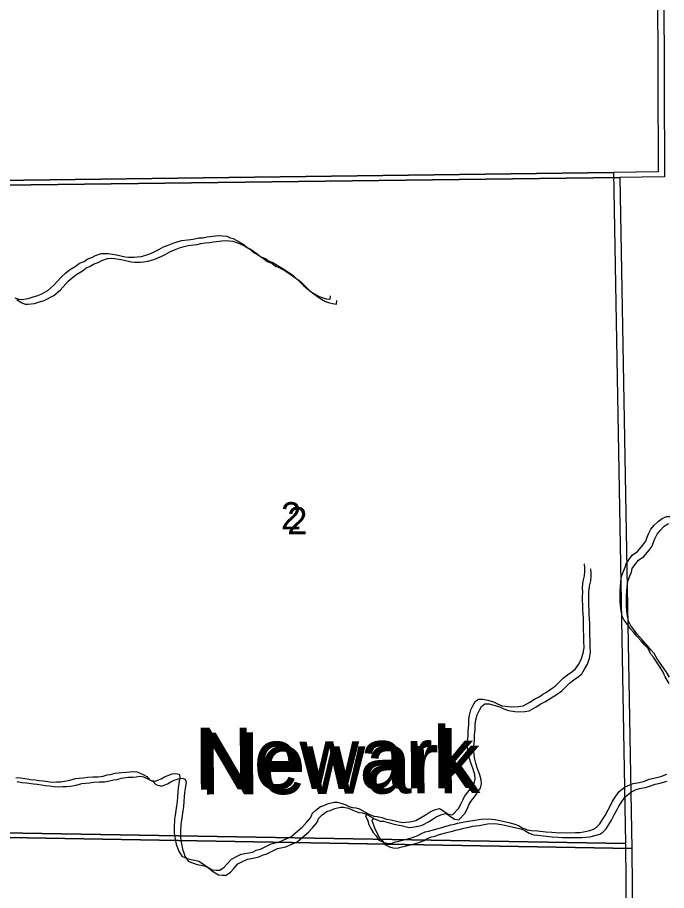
# Model space of a CAD drawing. Extents: x -21.1 to 50.3, y -4.9 to 22.1.
# Drawn here: x 48.245 to 49.24, y 18.636 to 19.975 of the extents above; entities that cross this region are included whole.
import ezdxf

# ---------------------------------------------------------------- set-up
doc = ezdxf.new("R2010")
doc.units = 0
for name, color, linetype in [('GM_X_Minor_River', 7, 'Continuous'), ('GM_X_Minor_River_Text', 7, 'Continuous'), ('GM_X_Section', 7, 'Continuous'), ('GM_X_Section_Text', 7, 'Continuous')]:
    doc.layers.add(name, color=color, linetype=linetype)

msp = doc.modelspace()

# ---------------------------------------------------------------- linework, layer by layer
at = {"layer": 'GM_X_Minor_River'}
for points in [[(48.4561, 19.6161), (48.4614, 19.6188), (48.4683, 19.623), (48.4755, 19.6257), (48.4831, 19.6288), (48.4907, 19.6311), (48.4964, 19.6327), (48.5051, 19.6335), (48.5105, 19.6343), (48.5162, 19.6354), (48.5226, 19.6366), (48.5291, 19.637), (48.5352, 19.6382), (48.5401, 19.6386), (48.5481, 19.6398), (48.5542, 19.6402), (48.5592, 19.6398), (48.5653, 19.6391), (48.5706, 19.6369), (48.5752, 19.6357), (48.5843, 19.6309), (48.5923, 19.6263), (48.5969, 19.6218), (48.603, 19.6188), (48.6122, 19.6124), (48.6176, 19.6079), (48.6248, 19.6053), (48.6306, 19.6011), (48.6359, 19.5989), (48.6451, 19.5936), (48.6531, 19.5887), (48.6619, 19.5827), (48.6665, 19.5793), (48.6714, 19.5747), (48.6772, 19.5691), (48.6829, 19.5638), (48.689, 19.5585), (48.6955, 19.5536), (48.7009, 19.5502), (48.707, 19.5468), (48.7131, 19.5446), (48.718, 19.5435), (48.7238, 19.5427), (48.7245, 19.5481)], [(48.4658, 19.6086), (48.4711, 19.6113), (48.4779, 19.6155), (48.4851, 19.6182), (48.4927, 19.6213), (48.5003, 19.6236), (48.506, 19.6252), (48.5148, 19.626), (48.5201, 19.6268), (48.5258, 19.6279), (48.5323, 19.6291), (48.5387, 19.6295), (48.5448, 19.6307), (48.5498, 19.6311), (48.5578, 19.6323), (48.5638, 19.6327), (48.5688, 19.6323), (48.5749, 19.6316), (48.5802, 19.6294), (48.5848, 19.6282), (48.594, 19.6234), (48.602, 19.6188), (48.6066, 19.6143), (48.6127, 19.6113), (48.6219, 19.6049), (48.6272, 19.6004), (48.6345, 19.5978), (48.6402, 19.5936), (48.6455, 19.5914), (48.6547, 19.5861), (48.6627, 19.5812), (48.6715, 19.5752), (48.6761, 19.5718), (48.6811, 19.5672), (48.6868, 19.5616), (48.6925, 19.5563), (48.6987, 19.551), (48.7052, 19.5461), (48.7105, 19.5427), (48.7166, 19.5393), (48.7227, 19.5371), (48.7277, 19.536), (48.7334, 19.5352), (48.7341, 19.5406)], [(48.2407, 19.545), (48.2464, 19.5428), (48.251, 19.5424), (48.2609, 19.5436), (48.2673, 19.5459), (48.2757, 19.5482), (48.281, 19.5506), (48.2863, 19.5536), (48.2909, 19.5559), (48.3004, 19.564), (48.3049, 19.5693), (48.3125, 19.5777), (48.3185, 19.5831), (48.3242, 19.5876), (48.3344, 19.5938), (48.3398, 19.598), (48.3466, 19.6007), (48.3515, 19.6041), (48.3595, 19.6072), (48.3644, 19.6095), (48.3728, 19.6126), (48.3789, 19.613), (48.3838, 19.6127), (48.3903, 19.6116), (48.3964, 19.6105), (48.4094, 19.6075), (48.4151, 19.6071), (48.4231, 19.6072), (48.428, 19.6076), (48.4349, 19.6084), (48.4444, 19.6111), (48.4501, 19.6134), (48.4561, 19.6161)], [(48.2438, 19.5424), (48.2503, 19.5375), (48.2561, 19.5353), (48.2606, 19.5349), (48.2705, 19.5361), (48.277, 19.5384), (48.2853, 19.5407), (48.2907, 19.5431), (48.296, 19.5461), (48.3005, 19.5484), (48.31, 19.5565), (48.3145, 19.5618), (48.3221, 19.5702), (48.3282, 19.5756), (48.3338, 19.5801), (48.3441, 19.5863), (48.3494, 19.5905), (48.3562, 19.5932), (48.3612, 19.5966), (48.3691, 19.5997), (48.3741, 19.602), (48.3824, 19.6051), (48.3885, 19.6055), (48.3935, 19.6052), (48.3999, 19.6041), (48.406, 19.6029), (48.419, 19.6), (48.4247, 19.5996), (48.4327, 19.5997), (48.4376, 19.6001), (48.4445, 19.6009), (48.454, 19.6036), (48.4597, 19.6059), (48.4658, 19.6086)], [(49.2436, 18.9537), (49.2374, 18.9636), (49.2343, 18.9708), (49.2297, 18.9787), (49.2251, 18.9852), (49.2194, 18.9939), (49.2155, 18.9988), (49.2113, 19.0071), (49.2063, 19.0124), (49.2006, 19.0188), (49.1941, 19.0264), (49.1891, 19.0321), (49.1845, 19.0374), (49.1807, 19.0423), (49.1749, 19.0506), (49.1718, 19.0567), (49.1695, 19.068), (49.1687, 19.0791), (49.1686, 19.0958), (49.1696, 19.1091), (49.17, 19.1144), (49.1711, 19.1193), (49.1741, 19.127), (49.1764, 19.1319), (49.1775, 19.1372), (49.1828, 19.1449), (49.1869, 19.1502), (49.1953, 19.1559), (49.2032, 19.1655), (49.2077, 19.1716), (49.21, 19.1777), (49.2122, 19.183), (49.2156, 19.1902), (49.2202, 19.1956), (49.2266, 19.2021), (49.233, 19.2063), (49.2395, 19.2094), (49.2448, 19.2098)], [(49.244, 18.9633), (49.2394, 18.9712), (49.2348, 18.9777), (49.229, 18.9864), (49.2252, 18.9913), (49.2209, 18.9996), (49.216, 19.0049), (49.2102, 19.0113), (49.2037, 19.0189), (49.1987, 19.0246), (49.1941, 19.0299), (49.1903, 19.0348), (49.1845, 19.0431), (49.1815, 19.0492), (49.1791, 19.0605), (49.1783, 19.0716), (49.1782, 19.0883), (49.1793, 19.1016), (49.1796, 19.1069), (49.1807, 19.1118), (49.1837, 19.1195), (49.186, 19.1244), (49.1871, 19.1297), (49.1924, 19.1374), (49.1965, 19.1427), (49.2049, 19.1484), (49.2128, 19.158), (49.2174, 19.1641), (49.2196, 19.1702), (49.2219, 19.1755), (49.2253, 19.1827), (49.2298, 19.1881), (49.2362, 19.1946), (49.2427, 19.1988)], [(49.1112, 19.0673), (49.1112, 19.0723), (49.1108, 19.0825), (49.1107, 19.0875), (49.1111, 19.0928), (49.111, 19.1015), (49.1118, 19.1103), (49.114, 19.1186), (49.1143, 19.1255), (49.1143, 19.1304), (49.1139, 19.1369)], [(49.1209, 19.0598), (49.1208, 19.0648), (49.1204, 19.075), (49.1204, 19.08), (49.1207, 19.0853), (49.1207, 19.094), (49.1214, 19.1028), (49.1236, 19.1111), (49.124, 19.118), (49.124, 19.1229), (49.1235, 19.1294)], [(48.596, 18.6934), (48.6048, 18.6953), (48.6105, 18.698), (48.6173, 18.6999), (48.6336, 18.708), (48.6462, 18.7107), (48.653, 18.7138), (48.6636, 18.7184), (48.6708, 18.7245), (48.6811, 18.7333), (48.6871, 18.7398), (48.6939, 18.7475), (48.6969, 18.7547), (48.7019, 18.7597), (48.7091, 18.765), (48.7144, 18.7666), (48.7212, 18.7696), (48.73, 18.7716), (48.7349, 18.7716), (48.7421, 18.7698), (48.7479, 18.7675), (48.7528, 18.7653), (48.7582, 18.7634), (48.7631, 18.763), (48.7688, 18.7615), (48.7822, 18.7536), (48.791, 18.7503), (48.7963, 18.7499), (48.8032, 18.7481), (48.8104, 18.7458), (48.8169, 18.7447), (48.8234, 18.7432), (48.8295, 18.7417), (48.8352, 18.7406), (48.8401, 18.741), (48.8493, 18.7422), (48.8553, 18.7438), (48.8648, 18.7492), (48.8709, 18.7526), (48.877, 18.7568), (48.8838, 18.7599), (48.8914, 18.7618), (48.8968, 18.7588), (48.9048, 18.7532), (48.9116, 18.7521), (48.9207, 18.762), (48.9245, 18.7685), (48.9271, 18.775), (48.9297, 18.7803), (48.9369, 18.7894), (48.9403, 18.7948), (48.9449, 18.8005), (48.9463, 18.8074), (48.9455, 18.8134), (48.9432, 18.8225), (48.9397, 18.832), (48.9378, 18.8388), (48.9362, 18.8449), (48.9351, 18.8514), (48.9346, 18.8586), (48.9346, 18.8658), (48.9353, 18.8734), (48.9357, 18.8818), (48.9364, 18.8905), (48.9367, 18.8985), (48.9378, 18.9053), (48.9397, 18.9133), (48.9434, 18.9202), (48.9464, 18.9259), (48.9514, 18.9297), (48.9578, 18.9297), (48.9655, 18.9279), (48.9742, 18.9253), (48.9803, 18.9223), (48.9876, 18.9196), (48.9975, 18.9182), (49.0024, 18.9178), (49.0127, 18.9183), (49.0196, 18.9194), (49.0302, 18.9252), (49.0374, 18.9298), (49.0446, 18.9333), (49.0499, 18.9371), (49.0556, 18.9405), (49.0609, 18.944), (49.0693, 18.9501), (49.0757, 18.9562), (49.0814, 18.9616), (49.0878, 18.9669), (49.0943, 18.9715), (49.0999, 18.9761), (49.1045, 18.983), (49.1086, 18.9906), (49.1116, 19.0001), (49.1135, 19.0085), (49.113, 19.0187), (49.113, 19.0244), (49.1125, 19.0377), (49.1125, 19.0533), (49.112, 19.0598), (49.1112, 19.0673)], [(48.6057, 18.6859), (48.6144, 18.6878), (48.6201, 18.6905), (48.6269, 18.6924), (48.6433, 18.7005), (48.6558, 18.7032), (48.6626, 18.7063), (48.6733, 18.7109), (48.6805, 18.717), (48.6907, 18.7258), (48.6968, 18.7323), (48.7036, 18.74), (48.7066, 18.7472), (48.7115, 18.7522), (48.7187, 18.7575), (48.724, 18.7591), (48.7309, 18.7621), (48.7396, 18.7641), (48.7445, 18.7641), (48.7518, 18.7623), (48.7575, 18.76), (48.7625, 18.7578), (48.7678, 18.7559), (48.7728, 18.7555), (48.7785, 18.754), (48.7918, 18.7461), (48.8006, 18.7428), (48.8059, 18.7424), (48.8128, 18.7406), (48.8201, 18.7383), (48.8265, 18.7372), (48.833, 18.7357), (48.8391, 18.7342), (48.8448, 18.7331), (48.8498, 18.7335), (48.8589, 18.7347), (48.865, 18.7363), (48.8745, 18.7417), (48.8805, 18.7451), (48.8866, 18.7493), (48.8934, 18.7524), (48.901, 18.7543), (48.9064, 18.7513), (48.9144, 18.7457), (48.9213, 18.7446), (48.9304, 18.7545), (48.9341, 18.761), (48.9367, 18.7675), (48.9394, 18.7728), (48.9466, 18.7819), (48.95, 18.7873), (48.9545, 18.793), (48.956, 18.7999), (48.9552, 18.8059), (48.9529, 18.815), (48.9494, 18.8245), (48.9474, 18.8313), (48.9459, 18.8374), (48.9447, 18.8439), (48.9443, 18.8511), (48.9442, 18.8583), (48.945, 18.8659), (48.9453, 18.8743), (48.946, 18.883), (48.9463, 18.891), (48.9474, 18.8978), (48.9493, 18.9058), (48.9531, 18.9127), (48.9561, 18.9184), (48.961, 18.9222), (48.9675, 18.9222), (48.9751, 18.9204), (48.9839, 18.9178), (48.99, 18.9148), (48.9972, 18.9121), (49.0071, 18.9107), (49.0121, 18.9103), (49.0224, 18.9108), (49.0292, 18.9119), (49.0398, 18.9177), (49.047, 18.9223), (49.0542, 18.9258), (49.0596, 18.9296), (49.0652, 18.933), (49.0706, 18.9365), (49.0789, 18.9426), (49.0853, 18.9487), (49.091, 18.9541), (49.0975, 18.9594), (49.1039, 18.964), (49.1096, 18.9686), (49.1141, 18.9755), (49.1183, 18.9831), (49.1213, 18.9926), (49.1231, 19.001), (49.1227, 19.0112), (49.1226, 19.0169), (49.1222, 19.0302), (49.1221, 19.0458), (49.1217, 19.0523), (49.1209, 19.0598)], [(48.2418, 18.8096), (48.249, 18.8088), (48.2593, 18.8074), (48.265, 18.8066), (48.2719, 18.8059), (48.2776, 18.8048), (48.284, 18.8045), (48.2909, 18.8034), (48.2974, 18.8026), (48.3042, 18.8031), (48.3107, 18.8031), (48.3164, 18.8039), (48.3248, 18.8055), (48.3335, 18.8078), (48.3392, 18.8086), (48.3453, 18.809), (48.3521, 18.8098), (48.3601, 18.8106), (48.3681, 18.8106), (48.3757, 18.8118), (48.3822, 18.8134), (48.3871, 18.8142), (48.3944, 18.8161), (48.4043, 18.8173), (48.4119, 18.8177), (48.4168, 18.8181), (48.4225, 18.8189), (48.4282, 18.8182), (48.437, 18.8141), (48.4427, 18.811), (48.4469, 18.8061), (48.455, 18.8039), (48.4599, 18.8054), (48.4648, 18.8074), (48.4701, 18.8104), (48.4751, 18.8127), (48.4815, 18.8151), (48.4872, 18.8158), (48.4922, 18.8147), (48.4937, 18.8098), (48.4919, 18.8003), (48.4908, 18.7938), (48.4904, 18.7874), (48.4897, 18.7801), (48.4894, 18.7726), (48.4879, 18.7623), (48.4865, 18.7516), (48.4853, 18.7456), (48.4847, 18.7323), (48.4847, 18.7243), (48.4863, 18.7152), (48.4878, 18.7072), (48.4898, 18.7015), (48.4917, 18.6966), (48.4967, 18.689), (48.5032, 18.686), (48.5104, 18.6838), (48.5165, 18.6827), (48.5226, 18.6812), (48.5284, 18.6778), (48.5352, 18.6725), (48.5429, 18.668), (48.5494, 18.6673), (48.5547, 18.6673), (48.5615, 18.6719), (48.5664, 18.6776), (48.5729, 18.6845), (48.5801, 18.6883), (48.5877, 18.6918), (48.596, 18.6934)], [(48.2442, 18.8035), (48.2514, 18.8021), (48.2586, 18.8013), (48.2689, 18.7999), (48.2746, 18.7991), (48.2815, 18.7984), (48.2872, 18.7973), (48.2937, 18.797), (48.3005, 18.7959), (48.307, 18.7951), (48.3139, 18.7956), (48.3203, 18.7956), (48.326, 18.7964), (48.3344, 18.798), (48.3431, 18.8003), (48.3488, 18.8011), (48.3549, 18.8015), (48.3618, 18.8023), (48.3698, 18.8031), (48.3778, 18.8031), (48.3854, 18.8043), (48.3918, 18.8059), (48.3968, 18.8067), (48.404, 18.8086), (48.4139, 18.8098), (48.4215, 18.8102), (48.4264, 18.8106), (48.4322, 18.8114), (48.4379, 18.8107), (48.4466, 18.8066), (48.4524, 18.8035), (48.4566, 18.7986), (48.4646, 18.7964), (48.4695, 18.7979), (48.4745, 18.7999), (48.4798, 18.8029), (48.4847, 18.8052), (48.4912, 18.8076), (48.4969, 18.8083), (48.5018, 18.8072), (48.5034, 18.8023), (48.5015, 18.7928), (48.5004, 18.7863), (48.5001, 18.7799), (48.4994, 18.7726), (48.499, 18.7651), (48.4976, 18.7548), (48.4961, 18.7441), (48.495, 18.7381), (48.4943, 18.7248), (48.4943, 18.7168), (48.4959, 18.7077), (48.4975, 18.6997), (48.4994, 18.694), (48.5013, 18.6891), (48.5063, 18.6815), (48.5128, 18.6785), (48.5201, 18.6763), (48.5262, 18.6752), (48.5323, 18.6737), (48.538, 18.6703), (48.5449, 18.665), (48.5525, 18.6605), (48.559, 18.6598), (48.5643, 18.6598), (48.5711, 18.6644), (48.5761, 18.6701), (48.5825, 18.677), (48.5897, 18.6808), (48.5973, 18.6843), (48.6057, 18.6859)], [(48.7806, 18.7546), (48.778, 18.751), (48.7815, 18.743), (48.7831, 18.7373), (48.7861, 18.7316), (48.7896, 18.7252), (48.7942, 18.7203), (48.798, 18.7142), (48.8053, 18.7105), (48.8102, 18.709), (48.8171, 18.7086), (48.8243, 18.7109), (48.8293, 18.7117), (48.835, 18.7133), (48.8429, 18.7156), (48.8502, 18.7175), (48.8581, 18.7206), (48.8631, 18.7233), (48.8695, 18.726), (48.8749, 18.7272), (48.8821, 18.7295), (48.8874, 18.731), (48.895, 18.733), (48.8999, 18.7345), (48.9091, 18.7369), (48.9144, 18.738), (48.9193, 18.7396), (48.9273, 18.7411), (48.9322, 18.7423), (48.9429, 18.7435), (48.9554, 18.7459), (48.9669, 18.7463), (48.9768, 18.7452), (48.9863, 18.743), (48.9977, 18.7404), (49.0069, 18.7382), (49.0126, 18.7359), (49.0195, 18.7318), (49.0263, 18.7292), (49.0328, 18.7284), (49.0416, 18.7277), (49.0545, 18.7263), (49.0637, 18.7256), (49.0698, 18.7252), (49.0762, 18.7249), (49.1002, 18.725), (49.1067, 18.7254), (49.1124, 18.7262), (49.1219, 18.7285), (49.1276, 18.7301), (49.1325, 18.7332), (49.1374, 18.7385), (49.1416, 18.745), (49.1454, 18.7515), (49.1499, 18.7598), (49.1544, 18.7678), (49.157, 18.7732), (49.1619, 18.7808), (49.1672, 18.7881), (49.1763, 18.7953), (49.1835, 18.7984), (49.1885, 18.8003), (49.1976, 18.8019), (49.2041, 18.8035), (49.2128, 18.8069), (49.2204, 18.8085), (49.231, 18.8112), (49.2402, 18.8147)], [(48.7902, 18.7471), (48.7877, 18.7435), (48.7911, 18.7355), (48.7927, 18.7298), (48.7958, 18.7241), (48.7992, 18.7177), (48.8038, 18.7128), (48.8077, 18.7067), (48.8149, 18.703), (48.8199, 18.7015), (48.8267, 18.7011), (48.834, 18.7034), (48.8389, 18.7042), (48.8446, 18.7058), (48.8526, 18.7081), (48.8598, 18.71), (48.8678, 18.7131), (48.8727, 18.7158), (48.8792, 18.7185), (48.8845, 18.7197), (48.8917, 18.722), (48.897, 18.7235), (48.9046, 18.7255), (48.9096, 18.727), (48.9187, 18.7294), (48.924, 18.7305), (48.929, 18.7321), (48.9369, 18.7336), (48.9419, 18.7348), (48.9525, 18.736), (48.9651, 18.7384), (48.9765, 18.7388), (48.9864, 18.7377), (48.9959, 18.7355), (49.0074, 18.7329), (49.0165, 18.7307), (49.0222, 18.7284), (49.0291, 18.7243), (49.036, 18.7217), (49.0424, 18.7209), (49.0512, 18.7202), (49.0642, 18.7188), (49.0733, 18.7181), (49.0794, 18.7177), (49.0859, 18.7174), (49.1098, 18.7175), (49.1163, 18.7179), (49.122, 18.7187), (49.1315, 18.721), (49.1372, 18.7226), (49.1422, 18.7257), (49.1471, 18.731), (49.1512, 18.7375), (49.155, 18.744), (49.1595, 18.7523), (49.164, 18.7603), (49.1667, 18.7657), (49.1716, 18.7733), (49.1769, 18.7806), (49.186, 18.7878), (49.1932, 18.7909), (49.1981, 18.7928), (49.2072, 18.7944), (49.2137, 18.796), (49.2224, 18.7994), (49.23, 18.801), (49.2407, 18.8037)]]:
    msp.add_lwpolyline(points, dxfattribs=at)
at = {"layer": 'GM_X_Section'}
for points in [[(48.2077, 20.7436), (49.2231, 20.7535), (49.2269, 19.7377), (49.1583, 19.7367), (48.2146, 19.7248)], [(48.2174, 20.7361), (49.2327, 20.746), (49.2366, 19.7302), (49.168, 19.7292), (48.2243, 19.7173)], [(48.2146, 19.7248), (49.1583, 19.7367), (49.1767, 18.7082), (48.1626, 18.7259), (48.1627, 19.7232)], [(48.2243, 19.7173), (49.168, 19.7292), (49.1863, 18.7007), (48.1722, 18.7184), (48.1723, 19.7157)], [(48.1626, 18.7259), (49.1767, 18.7082), (49.1854, 17.694), (48.7119, 17.7079), (48.171, 17.7091)], [(48.1722, 18.7184), (49.1863, 18.7007), (49.1951, 17.6865), (48.7215, 17.7004), (48.1806, 17.7016)]]:
    msp.add_lwpolyline(points, close=True, dxfattribs=at)

# ---------------------------------------------------------------- texts
at = {"layer": 'GM_X_Minor_River_Text'}
for p in [(48.5153, 18.7909), (48.5249, 18.7834)]:
    msp.add_text('Newark', height=0.09472, rotation=0.3148, dxfattribs=at).set_placement(p)
at = {"layer": 'GM_X_Section_Text'}
for p in [(48.6484, 19.1897), (48.658, 19.1822)]:
    msp.add_text('2', height=0.0419, rotation=0, dxfattribs=at).set_placement(p)

doc.saveas('drawing.dxf')
